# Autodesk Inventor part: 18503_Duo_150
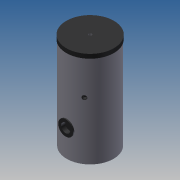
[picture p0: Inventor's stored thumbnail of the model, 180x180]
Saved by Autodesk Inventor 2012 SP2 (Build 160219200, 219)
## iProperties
allow_slope_adjustment: 0 ul
connection_type: 13 ul
flow_configuration2: 1 ul
flow_direction: 2 ul
loss_method: 0 ul
radius: 22,625 mm
description: 0:0:18502_Duo_150
manufacturer: 0:0:Flamco Group
model: 0:0:Duo 150
url: 0:0:www.flamcogroup.com
radius: 19,625 mm
radius: 15,375 mm
radius: 9,500 mm
Created: 2014-05
Part Number: 18503_Duo_150
Material: Default
Document SubType Name: Modeling
Designer: michel
Density: 1 g/cm^3
Author: michel
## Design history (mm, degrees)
sketch "Sketch1"
  geometry: C1 r 280 at (0, 0); 1 further point
  constraints: 1 centre point, 1 coincident
  dimensions: "d0" = 560 diameter of C1
extrude "Extrusion1" new body sketch "Sketch1" distance "d1" = 1150; taper "d2" = 0 deg
sketch "Sketch2"
  geometry: L1 (-280, 1150)-(280, 1150) reference; L2 (280, 0)-(280, 1150) reference; L3 (280, 1150)-(280, 1100); L4 (285, 1100)-(285, 1150); L5 (285, 1150)-(280, 1150); L6 (0, -208)-(0, 1248) reference; L7 (285, 1100)-(280, 1100); 1 further point
  constraints: 8 end point, 1 parallel
revolve "Revolution1" sketch "Sketch2" stored, may be unused: angle "d6" = 90 deg
workplane "Work Plane1"
workplane "Work Plane2"
workplane "Work Plane3"
workplane "Work Plane4"
workplane "Work Plane5"
workplane "Work Plane6"
sketch "Sketch3"
  geometry: L1 (404, 985)-(-394, 985) reference; L2 (404, 690)-(-394, 690) reference; L3 (404, 590)-(-394, 590) reference; L4 (404, 245)-(-394, 245) reference; L5 (404, 65)-(-394, 65) reference; L6 (280, 0)-(280, 1100) reference; L7 (290, 985)-(240, 985); L8 (240, 985)-(240, 1001.625); L9 (240, 1001.625)-(290, 1001.625); L10 (290, 1001.625)-(290, 985); L11 (290, 65)-(240, 65); L12 (240, 65)-(240, 81.625); L13 (240, 81.625)-(290, 81.625); L14 (290, 81.625)-(290, 65); L15 (280, 690)-(240, 690); L16 (240, 690)-(240, 700.475); L17 (240, 700.475)-(280, 700.475); L18 (280, 700.475)-(280, 690); L19 (280, 590)-(240, 590); L20 (240, 590)-(240, 606.625); L21 (240, 606.625)-(280, 606.625); L22 (280, 606.625)-(280, 590); L23 (240, 261.625)-(280, 261.625); L24 (280, 261.625)-(280, 245); L25 (280, 245)-(240, 245); L26 (240, 245)-(240, 261.625); 1 further point
  constraints: 40 end point, 8 parallel, 4 point on line, 3 horizontal, 3 perpendicular
  dimensions: "d13" = 50 distance of L8.end L9.end; "d14" = 16.625 distance of L7.end L8.end; "d15" = 50 distance of L12.end L13.end; "d16" = 16.625 distance of L11.end L12.end; "d17" = 40 distance of L16.end L17.end; "d18" = 10.475 distance of L15.end L16.end; "d19" = 40 distance of L20.end L21.end; "d20" = 16.625 distance of L19.end L20.end; "d21" = 40 distance of L23.start L23.end; "d22" = 16.625 distance of L25.end L23.start
revolve "Revolution2" stored, may be unused: angle "d23" = 90 deg
revolve "Revolution3" stored, may be unused: angle "d24" = 90 deg
revolve "Revolution4" stored, may be unused: angle "d25" = 90 deg
revolve "Revolution5" stored, may be unused: angle "d26" = 90 deg
revolve "Revolution6" stored, may be unused: angle "d27" = 90 deg
revolve "Revolution7" stored, may be unused: angle "d28" = 90 deg
revolve "Revolution8" stored, may be unused: angle "d29" = 90 deg
sketch "Sketch4"
  geometry: C1 r 16.625 at (0, 0) reference; C2 r 15.375 at (0, 0); 1 further point
  constraints: 1 centre point, 1 coincident
  dimensions: "d30" = 30.75 diameter of C2
extrude "Extrusion2" cut sketch "Sketch4" distance "d31" = 40; taper "d32" = 0 deg
sketch "Sketch5"
  geometry: C1 r 16.625 at (0, 0) reference; C2 r 15.375 at (0, 0); 1 further point
  constraints: 1 centre point, 1 coincident
  dimensions: "d33" = 30.75 diameter of C2
extrude "Extrusion3" cut sketch "Sketch5" distance "d34" = 40; taper "d35" = 0 deg
workplane "Work Plane7"
sketch "Sketch6"
  geometry: C1 r 9.5 at (0, 0); C2 r 16.625 at (0, -100) reference; C3 r 16.625 at (0, -445) reference; C4 r 15.375 at (0, -100); C5 r 15.375 at (0, -445); 7 further points
  constraints: 6 vertical alignment, 3 centre point, 2 coincident
  dimensions: "d36" = 19 diameter of C1; "d37" = 30.75 diameter of C4; "d38" = 30.75 diameter of C5
  node "Projected Loop1"
  node "Projected Loop2"
extrude "Extrusion4" join sketch "Sketch6" distance "d39" = 40; taper "d40" = 0 deg
extrude "Extrusion5" join sketch "Sketch6" distance "d41" = 40; taper "d42" = 0 deg
extrude "Extrusion6" join sketch "Sketch6" distance "d43" = 40; taper "d44" = 0 deg
workplane "Work Plane8"
workplane "Work Plane9"
sketch "Sketch7"
  geometry: L1 (394.5, 327)-(-407, 327) reference; L2 (-280, 0)-(-280, 1100) reference; L3 (-280, 327)-(-292.5, 327); L4 (-292.5, 327)-(-292.5, 417); L5 (-292.5, 417)-(-280, 417); L6 (-280, 417)-(-280, 327); 1 further point
  constraints: 8 end point, 2 parallel, 2 point on line, 1 horizontal, 1 perpendicular
  dimensions: "d47" = 12.5 distance of L4.end L5.end; "d48" = 90 distance of L3.end L4.end
revolve "Revolution9" sketch "Sketch7" stored, may be unused: angle "d49" = 90 deg
sketch "Sketch8"
  geometry: C1 r 62.5 at (0, 0); A1 r 90 centre (0, 0) between (0, -90) and (0, 90) reference; 1 further point
  constraints: 1 centre point, 1 coincident
  dimensions: "d50" = 125 diameter of C1
extrude "Extrusion7" join sketch "Sketch8" stored distance "d51" = 10; taper "d52" = 0 deg
sketch "Sketch9"
  geometry: C1 r 90 at (0, 0) reference; C2 r 55 at (0, 0); 1 further point
  constraints: 1 centre point, 1 coincident
  dimensions: "d53" = 110 diameter of C2
extrude "Extrusion8" cut sketch "Sketch9" distance "d54" = 50; taper "d55" = 0 deg
sketch "Sketch10"
  geometry: C1 r 285 at (0, 0) reference; C2 r 20.955 at (0, 0); C3 r 19.625 at (0, 0)
  constraints: 2 centre point, 2 coincident
  dimensions: "d56" = 41.91 diameter of C2; "d59" = 39.25 diameter of C3
extrude "Extrusion9" cut sketch "Sketch10" distance "d57" = 50; taper "d58" = 0 deg
extrude "Extrusion10" join sketch "Sketch10" distance "d60" = 50; taper "d61" = 0 deg
workplane "Work Plane10"
sketch "Sketch11"
  geometry: L1 (690, -545.95)-(690, 545.95) reference; L2 (0, 280)-(1100, 280) reference; L3 (690, 280)-(713.9, 280); L4 (713.9, 280)-(713.9, 240); L5 (713.9, 240)-(690, 240); L6 (690, 240)-(690, 280); L7 (667.375, 240)-(667.375, 280); L8 (667.375, 240)-(664.825, 240); L9 (664.825, 240)-(664.825, 280); L10 (667.375, 280)-(664.825, 280); 1 further point
  constraints: 16 end point, 4 perpendicular, 4 point on line, 2 parallel, 1 horizontal
  dimensions: "d63" = 23.9 distance of L4.end L5.end; "d64" = 40 distance of L3.end L4.end; "d67" = 22.625 distance of L5.end L7.start; "d68" = 2.55 distance of L7.start L8.end
revolve "Revolution10" stored, may be unused: angle "d65" = 90 deg
revolve "Revolution11" stored, may be unused: angle "d69" = 90 deg
body "Solid1"
other parameters: "d8" = -65, "d9" = -245, "d12" = 0, "d45" = -327, "d46" = 0, "d62" = 35 deg, "d72" = -985
